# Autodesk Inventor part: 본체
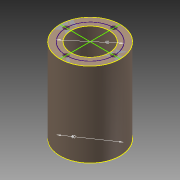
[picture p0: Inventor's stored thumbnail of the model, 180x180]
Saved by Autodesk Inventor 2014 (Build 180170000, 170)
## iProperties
Created: 2015-11
Part Number: 본체
Material: 일반
Document SubType Name: Modeling
Designer: 3sil_66666
Density: 1 g/cm^3
Appearance: 기본값
Author: 3sil_66666
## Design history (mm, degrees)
sketch "스케치1"
  geometry: C1 r 25 at (0, 0); C2 r 16 at (0, 0); 1 further point
  constraints: 2 centre point, 2 coincident
  dimensions: "d0" = 50 diameter of C1; "d1" = 32 diameter of C2
extrude "돌출1" new body sketch "스케치1" distance "d3" = 70; taper "d4" = 0 deg
sketch "스케치2"
  geometry: L1 (0, 25)-(0, -25); L2 (25, 0)-(-25, 0); C1 r 16 at (0, 0) reference; C2 r 20 at (0, 0); A1 r 25 centre (0, 0) between (0, 25) and (0, -25) reference
  constraints: 4 end point, 4 point on circle, 1 centre point, 1 coincident, 1 perpendicular, 1 vertical
  dimensions: "d5" = 40 diameter of C2
hole "구멍1" diameter "d8" = 4.5; stored, may be unused: countersink angle "d12" = 90 deg, drill point angle "d14" = 118 deg; dims "d6" = 10, "d7" = 10, "d9" = 6, "d10" = 4, "d11" = 2, "d13" = 8
feature "복합1"
sketch "스케치3"
  geometry: L1 (0, 25)-(0, -25); L2 (25, 0)-(-25, 0); C1 r 16 at (0, 0) reference; C2 r 20 at (0, 0); A1 r 25 centre (0, 0) between (0, 25) and (0, -25) reference
  constraints: 4 end point, 4 point on circle, 1 centre point, 1 coincident, 1 perpendicular, 1 vertical
  dimensions: "d18" = 40 diameter of C2
node "솔리드1"
pattern_circular "원형 패턴1" dims angle "d16" = 360 deg
node "곡면1"
